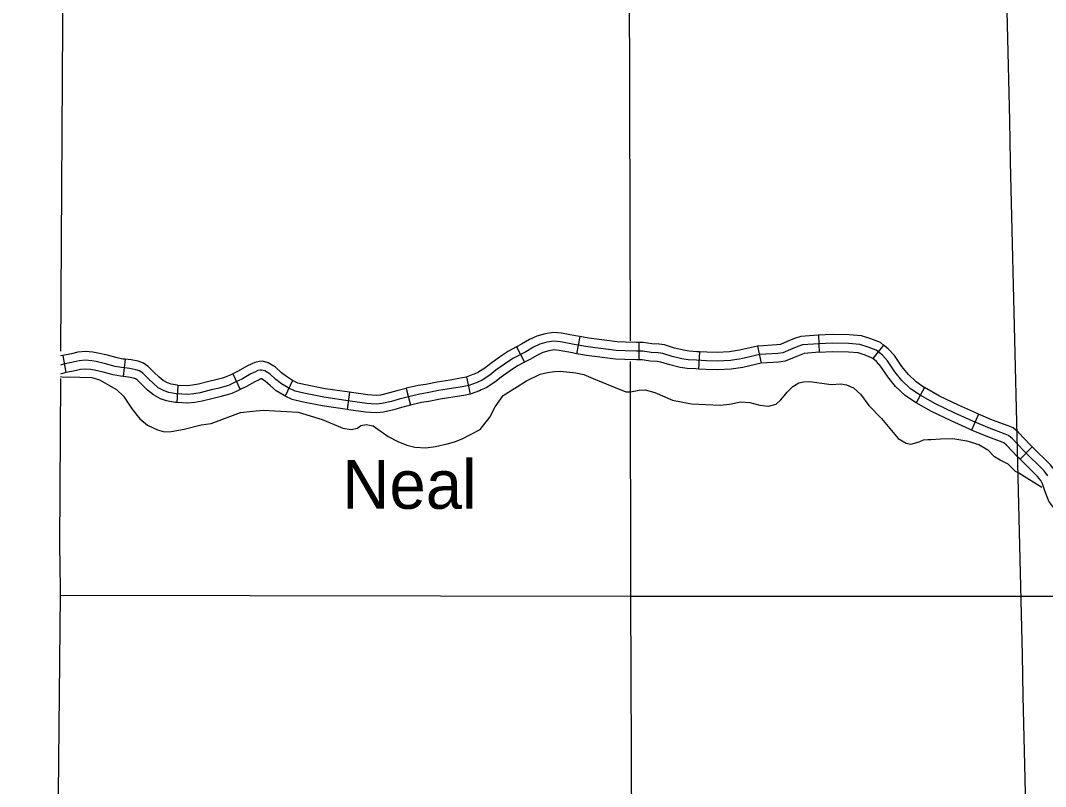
# Model space of a CAD drawing. Extents: x -19 to 366, y -4 to 359.
# Drawn here: x 133.386 to 135.065, y 194.735 to 195.99 of the extents above; entities that cross this region are included whole.
import ezdxf

# ---------------------------------------------------------------- set-up
doc = ezdxf.new("R2010")
doc.units = 0
for name, color, linetype in [('R_Alt Surface', 7, 'Continuous'), ('R_Axis Annot', 7, 'Continuous'), ('R_ROW Annot', 7, 'Continuous'), ('R_Temp Easement', 7, 'Continuous'), ('Sheet Fence', 7, 'Continuous')]:
    doc.layers.add(name, color=color, linetype=linetype)

msp = doc.modelspace()

# ---------------------------------------------------------------- linework, layer by layer
at = {"layer": 'R_Alt Surface'}
for points in [[(133.4577, 196.4009), (133.4555, 196.0827), (133.4555, 196.0738), (133.4519, 195.4487)], [(133.4517, 195.4038), (133.4501, 195.1311), (133.451, 195.0596), (133.4509, 195.0489), (133.448, 194.7237), (133.4475, 194.6633)]]:
    msp.add_lwpolyline(points, dxfattribs=at)
at = {"layer": 'R_Axis Annot'}
for points in [[(134.3834, 196.0617), (134.3847, 195.4655)], [(134.3848, 195.4314), (134.3857, 195.0473)], [(133.4509, 195.0489), (134.3857, 195.0473)], [(134.3857, 195.0473), (135.1861, 195.0471)], [(134.3857, 195.0473), (134.3877, 194.5307)]]:
    msp.add_lwpolyline(points, dxfattribs=at)
at = {"layer": 'R_ROW Annot'}
for p, q in [((134.3024, 195.4723), (134.2972, 195.4443)), ((134.6934, 195.4749), (134.6943, 195.4465)), ((134.1985, 195.4555), (134.2119, 195.4304)), ((134.3991, 195.4626), (134.3993, 195.4342)), ((134.5934, 195.4565), (134.5997, 195.4288)), ((134.8001, 195.4584), (134.7822, 195.4363)), ((133.4556, 195.4416), (133.4606, 195.4136)), ((133.5577, 195.4352), (133.5546, 195.4069)), ((134.4985, 195.4474), (134.4966, 195.419)), ((133.734, 195.4114), (133.7459, 195.3856)), ((133.832, 195.4005), (133.8196, 195.3749)), ((134.1166, 195.4061), (134.1227, 195.3783)), ((133.6437, 195.3925), (133.6424, 195.3642)), ((134.0178, 195.3876), (134.025, 195.3601)), ((134.8671, 195.3887), (134.8533, 195.3638)), ((133.9253, 195.3812), (133.9212, 195.3531)), ((134.9556, 195.3453), (134.9443, 195.3192)), ((135.0436, 195.2916), (135.0237, 195.2714))]:
    msp.add_line(p, q, dxfattribs=at)
for points in [[(134.3024, 195.4723), (134.2956, 195.4735), (134.2724, 195.4781), (134.2591, 195.4791), (134.2454, 195.4769), (134.2321, 195.4731), (134.2199, 195.4674), (134.2069, 195.46), (134.1985, 195.4555)], [(134.3991, 195.4626), (134.3954, 195.4626), (134.3771, 195.463), (134.3636, 195.4639), (134.3174, 195.4695), (134.3024, 195.4723)], [(134.6933, 195.4749), (134.693, 195.4749), (134.6643, 195.4726), (134.6543, 195.4693), (134.6422, 195.4641), (134.6313, 195.4596), (134.6252, 195.4587), (134.5953, 195.4569), (134.5934, 195.4565)], [(134.8001, 195.4584), (134.7949, 195.4626), (134.7793, 195.4687), (134.7638, 195.4736), (134.7438, 195.475), (134.7159, 195.4756), (134.6934, 195.4749)], [(134.1985, 195.4555), (134.1855, 195.4485), (134.1708, 195.4387), (134.1565, 195.4285), (134.1467, 195.4209), (134.1356, 195.4137), (134.1292, 195.4109), (134.1273, 195.41), (134.1165, 195.4061), (134.1166, 195.4061)], [(135.0692, 195.2445), (135.063, 195.2527), (135.0297, 195.2854), (135.0113, 195.3048), (135.0047, 195.3106), (134.9991, 195.3128), (134.9734, 195.3222), (134.9464, 195.3338), (134.9165, 195.3472), (134.8851, 195.3624), (134.8598, 195.3764), (134.8443, 195.387), (134.8301, 195.4005), (134.8186, 195.4149), (134.8065, 195.4325), (134.7981, 195.4417), (134.7877, 195.4502), (134.7746, 195.4553), (134.7611, 195.4595), (134.7431, 195.4608), (134.7159, 195.4614), (134.6938, 195.4607), (134.6671, 195.4586), (134.6594, 195.456), (134.6477, 195.451), (134.635, 195.4458), (134.6266, 195.4446), (134.5973, 195.4428), (134.5667, 195.4359), (134.5492, 195.4333), (134.5275, 195.4322), (134.5101, 195.4324), (134.4933, 195.4335), (134.48, 195.4342), (134.4696, 195.436), (134.4539, 195.4396), (134.4382, 195.4447), (134.431, 195.4456), (134.4191, 195.4464), (134.4054, 195.4485), (134.3953, 195.4484), (134.3765, 195.4488), (134.3622, 195.4497), (134.3153, 195.4554), (134.2929, 195.4596), (134.2705, 195.464), (134.2596, 195.4648), (134.2484, 195.4631), (134.2371, 195.4597), (134.2264, 195.4548), (134.2138, 195.4475), (134.1928, 195.4363), (134.1789, 195.427), (134.1649, 195.4171), (134.1549, 195.4093), (134.1423, 195.4011), (134.1351, 195.3979)], [(134.2972, 195.4443), (134.2902, 195.4456), (134.2686, 195.4498), (134.2602, 195.4505), (134.2515, 195.4492), (134.2421, 195.4464), (134.233, 195.4422), (134.2207, 195.4351), (134.2119, 195.4304)], [(134.4985, 195.4474), (134.4942, 195.4476), (134.4816, 195.4483), (134.4724, 195.4499), (134.4577, 195.4533), (134.4413, 195.4586), (134.4324, 195.4597), (134.4206, 195.4605), (134.4064, 195.4627), (134.3991, 195.4626)], [(134.5934, 195.4565), (134.5641, 195.4499), (134.5478, 195.4475), (134.5272, 195.4464), (134.5106, 195.4466), (134.4985, 195.4474)], [(134.8673, 195.3885), (134.8532, 195.3981), (134.8406, 195.4101), (134.83, 195.4233), (134.8177, 195.4414), (134.8078, 195.4521), (134.8001, 195.4584)], [(134.1351, 195.3979), (134.1327, 195.3968), (134.1205, 195.3924), (134.1097, 195.39), (134.0922, 195.3871), (134.0711, 195.3838), (134.0525, 195.3801), (134.0404, 195.3781), (134.0215, 195.3739), (134.0065, 195.3699), (133.9941, 195.3663), (133.9783, 195.3625), (133.9693, 195.3617), (133.9607, 195.362), (133.9533, 195.3628), (133.9261, 195.3667), (133.883, 195.373), (133.8503, 195.3796), (133.8359, 195.3828), (133.8247, 195.3882), (133.8135, 195.3952), (133.8047, 195.4023), (133.7952, 195.4109), (133.7863, 195.4161), (133.7809, 195.4176), (133.7789, 195.4175), (133.775, 195.4166), (133.771, 195.4146), (133.7633, 195.4111), (133.7497, 195.4029), (133.7354, 195.3964), (133.7269, 195.3925), (133.7209, 195.3905), (133.7093, 195.3876), (133.6984, 195.3849), (133.6807, 195.3804), (133.6701, 195.3787), (133.6597, 195.3776), (133.6412, 195.3784), (133.6292, 195.3807), (133.6214, 195.3834), (133.6118, 195.3886), (133.6038, 195.3953), (133.5954, 195.4035), (133.5863, 195.4124), (133.581, 195.4161), (133.5752, 195.4181), (133.5651, 195.4201), (133.5518, 195.4215), (133.5411, 195.4235), (133.5252, 195.4279), (133.51, 195.4313), (133.503, 195.4326), (133.4926, 195.4335), (133.4824, 195.4327), (133.4727, 195.4302), (133.4567, 195.4273), (133.4518, 195.4257)], [(133.4556, 195.4416), (133.4519, 195.4409)], [(133.5577, 195.4352), (133.5538, 195.4356), (133.5443, 195.4373), (133.5287, 195.4417), (133.5128, 195.4453), (133.5048, 195.4466), (133.4927, 195.4477), (133.4801, 195.4468), (133.4696, 195.4441), (133.4556, 195.4416)], [(133.6437, 195.3925), (133.6428, 195.3926), (133.6328, 195.3945), (133.6271, 195.3964), (133.6199, 195.4004), (133.6133, 195.4059), (133.6053, 195.4136), (133.5954, 195.4234), (133.5875, 195.4288), (133.579, 195.4319), (133.5673, 195.4341), (133.5577, 195.4352)], [(134.3993, 195.4342), (134.3952, 195.4342), (134.3759, 195.4346), (134.3609, 195.4356), (134.3131, 195.4414), (134.2972, 195.4443)], [(134.4966, 195.419), (134.4925, 195.4193), (134.4784, 195.4201), (134.4668, 195.422), (134.4501, 195.4259), (134.435, 195.4307), (134.4296, 195.4315), (134.4175, 195.4323), (134.4044, 195.4343), (134.3993, 195.4342)], [(134.6946, 195.4466), (134.67, 195.4445), (134.6644, 195.4427), (134.6533, 195.4379), (134.6388, 195.4319), (134.628, 195.4304), (134.5993, 195.4287), (134.5997, 195.4288)], [(134.7822, 195.4363), (134.7804, 195.4378), (134.7699, 195.4419), (134.7585, 195.4455), (134.7424, 195.4466), (134.716, 195.4472), (134.6943, 195.4465)], [(134.8533, 195.3638), (134.8524, 195.3643), (134.8354, 195.3759), (134.8196, 195.3908), (134.8072, 195.4064), (134.7954, 195.4236), (134.7883, 195.4314), (134.7822, 195.4363)], [(133.5546, 195.4069), (133.5498, 195.4075), (133.5379, 195.4096), (133.5217, 195.4141), (133.5072, 195.4174), (133.5011, 195.4185), (133.4925, 195.4192), (133.4847, 195.4187), (133.4757, 195.4163), (133.4606, 195.4136)], [(133.832, 195.4005), (133.8316, 195.4006), (133.8217, 195.4068), (133.8139, 195.4131), (133.8037, 195.4224), (133.7919, 195.4293), (133.7826, 195.4319), (133.777, 195.4317), (133.7702, 195.43), (133.7649, 195.4275), (133.7567, 195.4237), (133.743, 195.4155), (133.734, 195.4114)], [(134.2119, 195.4304), (134.2001, 195.4242), (134.1869, 195.4153), (134.1734, 195.4057), (134.1632, 195.3977), (134.1491, 195.3886), (134.141, 195.385), (134.1381, 195.3837), (134.1244, 195.3787), (134.1227, 195.3783)], [(134.5997, 195.4288), (134.5693, 195.4219), (134.5506, 195.4192), (134.5278, 195.418), (134.5096, 195.4182), (134.4966, 195.419)], [(133.4606, 195.4136), (133.4602, 195.4135), (133.4517, 195.4107)], [(133.6424, 195.3642), (133.6395, 195.3643), (133.6256, 195.367), (133.6157, 195.3703), (133.6038, 195.3768), (133.5943, 195.3848), (133.5855, 195.3933), (133.5773, 195.4014), (133.5745, 195.4033), (133.5714, 195.4044), (133.563, 195.406), (133.5546, 195.4069)], [(133.734, 195.4114), (133.7295, 195.4093), (133.7217, 195.4057), (133.7169, 195.4041), (133.7059, 195.4014), (133.6949, 195.3986), (133.6778, 195.3944), (133.6682, 195.3928), (133.6593, 195.3918), (133.6437, 195.3925)], [(133.8196, 195.3749), (133.8179, 195.3757), (133.8052, 195.3836), (133.7955, 195.3915), (133.7868, 195.3993), (133.7807, 195.4029), (133.7798, 195.4032), (133.777, 195.4018), (133.7699, 195.3985), (133.7563, 195.3904), (133.7459, 195.3856)], [(133.9253, 195.3812), (133.8854, 195.387), (133.8532, 195.3935), (133.8406, 195.3963), (133.832, 195.4005)], [(134.1166, 195.4061), (134.107, 195.404), (134.0899, 195.4011), (134.0686, 195.3977), (134.05, 195.3941), (134.0377, 195.3921), (134.0182, 195.3877), (134.0178, 195.3876)], [(133.7459, 195.3856), (133.7414, 195.3835), (133.7322, 195.3793), (133.7248, 195.3768), (133.7127, 195.3739), (133.7018, 195.3711), (133.6836, 195.3665), (133.672, 195.3646), (133.6601, 195.3633), (133.6424, 195.3642)], [(134.0178, 195.3876), (134.0027, 195.3836), (133.9905, 195.38), (133.976, 195.3766), (133.9689, 195.3759), (133.9618, 195.3762), (133.9551, 195.3769), (133.9282, 195.3807), (133.9253, 195.3812)], [(134.9556, 195.3453), (134.9521, 195.3468), (134.9225, 195.3601), (134.8917, 195.375), (134.8671, 195.3887)], [(133.9212, 195.3531), (133.8806, 195.359), (133.8473, 195.3657), (133.8311, 195.3693), (133.8196, 195.3749)], [(134.1227, 195.3783), (134.1124, 195.3761), (134.0945, 195.373), (134.0735, 195.3698), (134.0551, 195.3661), (134.0431, 195.3642), (134.0249, 195.3601), (134.025, 195.3601)], [(134.025, 195.3601), (134.0103, 195.3563), (133.9978, 195.3526), (133.9806, 195.3485), (133.9697, 195.3474), (133.9597, 195.3478), (133.9516, 195.3487), (133.9241, 195.3526), (133.9212, 195.3531)], [(134.9443, 195.3192), (134.9406, 195.3208), (134.9105, 195.3343), (134.8786, 195.3498), (134.8533, 195.3638)], [(135.0436, 195.2916), (135.0399, 195.2953), (135.0211, 195.3151), (135.0121, 195.323), (135.0041, 195.3261), (134.9787, 195.3354), (134.9556, 195.3453)], [(135.0237, 195.2714), (135.0196, 195.2754), (135.0014, 195.2946), (134.9972, 195.2983), (134.9941, 195.2995), (134.9682, 195.309), (134.9443, 195.3192)], [(135.1013, 195.2086), (135.0976, 195.2142), (135.0962, 195.2162), (135.091, 195.2294), (135.0866, 195.2432), (135.0809, 195.2526), (135.0736, 195.2621), (135.0436, 195.2916)], [(135.0778, 195.1928), (135.074, 195.1983), (135.0709, 195.2029), (135.0642, 195.2198), (135.0605, 195.2314), (135.0574, 195.2365), (135.0523, 195.2432), (135.0237, 195.2714)]]:
    msp.add_lwpolyline(points, dxfattribs=at)
at = {"layer": 'R_Temp Easement'}
for points in [[(134.2609, 195.415), (134.2707, 195.4158), (134.296, 195.413), (134.3089, 195.4101), (134.3279, 195.402), (134.378, 195.382), (134.3852, 195.3817), (134.3995, 195.3845), (134.4093, 195.3849), (134.4253, 195.3809), (134.4545, 195.3683), (134.4852, 195.3622), (134.5324, 195.36), (134.5475, 195.3617), (134.5664, 195.3656), (134.5808, 195.3646), (134.5971, 195.3603), (134.6115, 195.3585), (134.6239, 195.3617), (134.6318, 195.3689), (134.6422, 195.3815), (134.6516, 195.3904), (134.661, 195.3965), (134.6689, 195.3985), (134.6791, 195.3986), (134.7143, 195.394), (134.7298, 195.3949), (134.7393, 195.3931), (134.7507, 195.3883), (134.7621, 195.3778), (134.7759, 195.3594), (134.7965, 195.3383), (134.8237, 195.3052), (134.8373, 195.2978), (134.8445, 195.2963), (134.8585, 195.2999), (134.8653, 195.303), (134.8727, 195.3036)], [(133.4517, 195.407), (133.4566, 195.4061), (133.4637, 195.4064), (133.503, 195.4056), (133.5155, 195.4016), (133.5432, 195.3859), (133.5551, 195.3747), (133.5692, 195.3536), (133.5815, 195.3374), (133.5944, 195.3273), (133.6104, 195.3195), (133.6221, 195.3166), (133.6331, 195.3167), (133.6542, 195.3207), (133.6821, 195.3278), (133.6984, 195.3302), (133.7466, 195.3481), (133.7667, 195.3504), (133.7836, 195.3517), (133.8408, 195.3485), (133.8804, 195.3368), (133.8999, 195.3284), (133.9143, 195.3225), (133.9276, 195.3203), (133.9381, 195.3223), (133.9438, 195.3269), (133.9524, 195.3285), (133.9638, 195.3264), (133.9885, 195.3088), (134.0045, 195.3006), (134.0193, 195.2943), (134.0322, 195.291), (134.05, 195.2904), (134.0658, 195.2925), (134.0851, 195.2965), (134.0971, 195.3), (134.1099, 195.3051), (134.1393, 195.3201), (134.155, 195.3404), (134.1639, 195.3575), (134.1766, 195.3758), (134.2153, 195.3997), (134.2375, 195.4106), (134.2495, 195.4137), (134.2609, 195.415)], [(134.8727, 195.3036), (134.8774, 195.3037), (134.8935, 195.3048), (134.9135, 195.3054), (134.9366, 195.3018), (134.956, 195.2955), (134.9708, 195.2869), (134.982, 195.2755)], [(135.0595, 195.2254), (135.0218, 195.2487), (135.0161, 195.2516), (135.0043, 195.2634), (134.991, 195.2697), (134.982, 195.2755)]]:
    msp.add_lwpolyline(points, dxfattribs=at)
at = {"layer": 'Sheet Fence'}
for points in [[(139.4406, 1.5315), (139.2511, 10.1473), (139.0608, 18.7633), (138.8699, 27.3793), (138.6784, 35.9956), (138.4861, 44.6119), (138.2932, 53.2285), (138.0997, 61.8451), (137.9055, 70.4619), (137.7106, 79.0789), (137.5151, 87.6959), (137.319, 96.3132), (137.1221, 104.9306), (136.9247, 113.5481), (136.7265, 122.1658), (136.5278, 130.7836), (136.3283, 139.4016), (136.1282, 148.0197), (135.9275, 156.6379), (135.7261, 165.2564), (135.5241, 173.8749), (135.3214, 182.4936), (135.1181, 191.1125), (134.9141, 199.7315), (134.7095, 208.3506), (134.5043, 216.9699), (134.2984, 225.5894), (134.0919, 234.209), (133.8847, 242.8288), (133.6769, 251.4487), (133.4685, 260.0687), (133.2594, 268.6889), (133.0497, 277.3093), (132.8393, 285.9298), (132.6283, 294.5504), (132.4167, 303.1713), (132.2044, 311.7922), (131.9916, 320.4133), (131.778, 329.0346), (131.5639, 337.656), (131.3491, 346.2776)], [(0, 189.5162), (7.1121, 189.5206), (14.2243, 189.5339), (21.3364, 189.556), (28.4484, 189.5869), (35.5605, 189.6267), (42.6725, 189.6754), (49.7844, 189.7329), (56.8962, 189.7992), (64.0079, 189.8744), (71.1196, 189.9584), (78.2311, 190.0512), (85.3425, 190.1529), (92.4538, 190.2635), (99.5649, 190.3829), (106.6759, 190.5111), (113.7867, 190.6482), (120.8974, 190.7941), (128.0078, 190.9489), (135.1181, 191.1125), (142.2282, 191.2849), (149.338, 191.4662), (156.4476, 191.6563), (163.5569, 191.8553), (170.666, 192.0631), (177.7749, 192.2798), (184.8835, 192.5053), (191.9917, 192.7396), (199.0997, 192.9828), (206.2074, 193.2348), (213.3147, 193.4956), (220.4218, 193.7653), (227.5285, 194.0438), (234.6348, 194.3312), (241.7408, 194.6274), (248.8464, 194.9324), (255.9516, 195.2463), (263.0564, 195.569), (270.1608, 195.9005), (277.2648, 196.2409), (284.3683, 196.5901), (291.4715, 196.9481), (298.5741, 197.315), (305.6763, 197.6907), (312.7781, 198.0753), (319.8793, 198.4686), (326.9801, 198.8708), (334.0804, 199.2818), (341.1801, 199.7017)]]:
    msp.add_spline(points, degree=3, dxfattribs=at)

# ---------------------------------------------------------------- texts
at = {"layer": 'R_Temp Easement'}
msp.add_text('Neal', height=0.08, dxfattribs=at).set_placement((133.9133, 195.1903))

doc.saveas('drawing.dxf')
